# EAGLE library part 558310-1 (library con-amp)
AMP connector
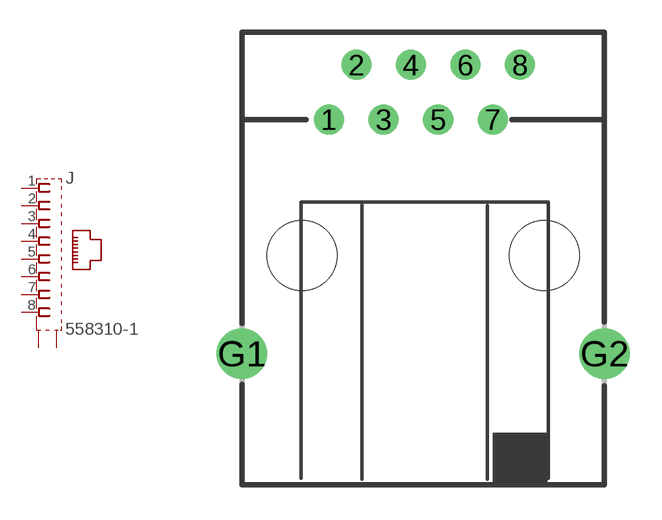
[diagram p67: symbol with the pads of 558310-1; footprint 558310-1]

Designator prefix J

## 558310-1 (MPN: 5558310-1; OC_FARNELL: unknown; OC_NEWARK: 40P9789)  [558310-1]
1  1  pas
2  2  pas
3  3  pas
4  4  pas
5  5  pas
6  6  pas
7  7  pas
8  8  pas
G1  S2  pas
G2  S1  pas

## Footprint 558310-1 (pad centres in mm)
Modular Jack Keyed Shielded
drill 0.889 round: 1 -4.445,6.35; 2 -3.175,8.89; 3 -1.905,6.35; 4 -0.635,8.89; 5 0.635,6.35; 6 1.905,8.89; 7 3.175,6.35; 8 4.445,8.89
drill 1.575 pad 2.184 round: G1 -8.509,-4.572; G2 8.382,-4.572
hole 3.251 at -5.715,0
hole 3.251 at 5.588,0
